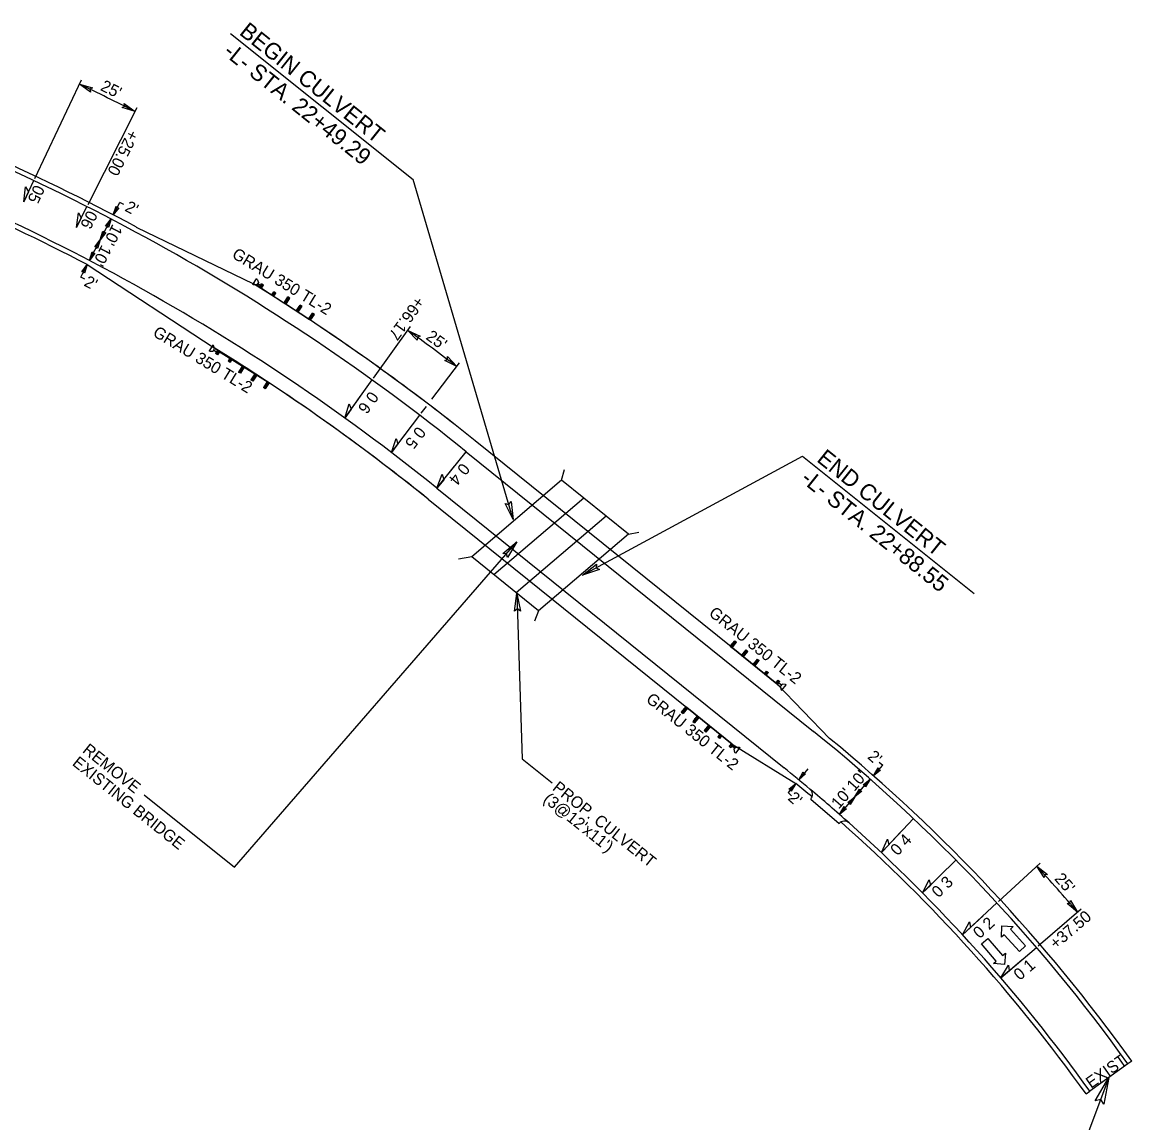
# Model space of a CAD drawing. Extents: x 1734344 to 1735097, y 915059 to 915850.
# Drawn here: x 1734622.6 to 1735096.6, y 915380.2 to 915850.3 of the extents above; entities that cross this region are included whole.
import ezdxf

# ---------------------------------------------------------------- set-up
doc = ezdxf.new("R2010")
doc.units = 0
for name, color, linetype in [('Prop Dimension Text', 7, 'Continuous'), ('Prop DSN Text', 7, 'Continuous'), ('Prop EOT', 7, 'Continuous'), ('Prop Guardrail', 7, 'Continuous'), ('Prop Guardrail Anchor Unit CELL', 7, 'Continuous'), ('Prop Lane Arrow CELL', 7, 'Continuous'), ('Prop Lane Lines', 7, 'Continuous'), ('Prop Paved Shoulder', 7, 'Continuous'), ('Prop Roadway Bridge', 7, 'Continuous'), ('Prop Roadway Culvert', 7, 'Continuous'), ('Prop Superelevation  Arrow CELL', 7, 'Continuous'), ('Prop Superelevation Label', 7, 'Continuous')]:
    doc.layers.add(name, color=color, linetype=linetype)

msp = doc.modelspace()

# ---------------------------------------------------------------- linework, layer by layer
at = {"layer": 'Prop Dimension Text'}
for p, q in [((1734628.03, 915783.6), (1734647.92, 915825.64)), ((1734650.75, 915772.47), (1734671.78, 915813.95)), ((1734661.54, 915768.03), (1734664.32, 915773.35)), ((1734666.09, 915772.42), (1734664.32, 915773.35)), ((1734655.98, 915757.4), (1734660.61, 915766.26)), ((1734651.35, 915748.54), (1734655.98, 915757.4)), ((1734647.64, 915741.45), (1734650.42, 915746.76)), ((1734649.41, 915740.52), (1734647.64, 915741.45)), ((1734772.69, 915698.31), (1734788.52, 915720.31)), ((1734797.66, 915689.34), (1734809.45, 915704.82)), ((1734793.03, 915683.26), (1734795.3, 915686.24)), ((1734958.13, 915531.38), (1734954.31, 915526.75)), ((1734986.19, 915528.48), (1734990.16, 915532.98)), ((1734988.65, 915534.31), (1734990.16, 915532.98)), ((1734953.04, 915525.2), (1734949.78, 915521.26)), ((1734978.26, 915519.47), (1734984.87, 915526.98)), ((1734949.78, 915521.26), (1734951.26, 915519.95)), ((1734971.65, 915511.97), (1734978.26, 915519.47)), ((1735039.68, 915474.79), (1735057.45, 915491.15)), ((1735056.55, 915455.82), (1735074.88, 915471.56))]:
    msp.add_line(p, q, dxfattribs=at)
for centre, radius, start, end in [((1734232.02, 914946.54), 970.51, 63.11588, 64.68134), ((1734232.02, 914946.54), 951.11, 52.71059, 54.27605), ((1734505.77, 914982.84), 748.16, 40.65421, 42.65756)]:
    msp.add_arc(centre, radius, start, end, dxfattribs=at)
at = {"layer": 'Prop DSN Text'}
for p, q in [((1734711.64, 915845.44), (1734789.56, 915783.08)), ((1734832.37, 915637.89), (1734789.56, 915783.08)), ((1734861.88, 915614.11), (1734955.89, 915664.98)), ((1734955.89, 915664.98), (1735029.28, 915606.25)), ((1734713.31, 915489.41), (1734833.87, 915628.32)), ((1734833.97, 915606.36), (1734836.16, 915535.68)), ((1734836.16, 915535.68), (1734848.98, 915525.41)), ((1734674.76, 915520.27), (1734713.31, 915489.41)), ((1735086.81, 915399.52), (1734968.27, 915084.45))]:
    msp.add_line(p, q, dxfattribs=at)
for points in [[(1734651.79, 915820.49), (1734647.06, 915823.83), (1734652.64, 915822.3), (1734651.58, 915821.69)], [(1734666.24, 915815.64), (1734670.87, 915812.17), (1734665.33, 915813.85), (1734666.41, 915814.43)], [(1734663.89, 915771.09), (1734661.54, 915768.03), (1734662.71, 915771.71), (1734663.09, 915770.99)], [(1734658.26, 915763.2), (1734660.61, 915766.26), (1734659.44, 915762.58), (1734659.07, 915763.3)], [(1734653.63, 915754.34), (1734655.98, 915757.4), (1734654.81, 915753.72), (1734654.44, 915754.44)], [(1734658.33, 915760.46), (1734655.98, 915757.4), (1734657.15, 915761.08), (1734657.53, 915760.35)], [(1734653.7, 915751.6), (1734651.35, 915748.54), (1734652.52, 915752.21), (1734652.89, 915751.49)], [(1734648.07, 915743.7), (1734650.42, 915746.76), (1734649.25, 915743.09), (1734648.88, 915743.81)], [(1734791.4, 915714.55), (1734787.35, 915718.69), (1734792.57, 915716.17), (1734791.41, 915715.77)], [(1734804.31, 915707.48), (1734808.24, 915703.23), (1734803.1, 915705.89), (1734804.26, 915706.26)], [(1734831.5, 915645.56), (1734832.37, 915637.89), (1734828.94, 915644.8), (1734830.48, 915644.28)], [(1734827.88, 915623.45), (1734833.87, 915628.32), (1734829.89, 915621.71), (1734829.5, 915623.28)], [(1734869.2, 915616.55), (1734861.88, 915614.11), (1734867.93, 915618.9), (1734867.75, 915617.28)], [(1734832.87, 915598.72), (1734833.97, 915606.36), (1734835.54, 915598.8), (1734834.18, 915599.7)], [(1734957.24, 915529.26), (1734954.31, 915526.75), (1734956.21, 915530.1), (1734956.43, 915529.32)], [(1734989.2, 915530.89), (1734986.19, 915528.48), (1734988.2, 915531.77), (1734988.39, 915530.98)], [(1734950.1, 915522.7), (1734953.04, 915525.2), (1734951.13, 915521.85), (1734950.92, 915522.63)], [(1734981.86, 915524.57), (1734984.87, 915526.98), (1734982.86, 915523.68), (1734982.66, 915524.48)], [(1734981.27, 915521.89), (1734978.26, 915519.47), (1734980.27, 915522.77), (1734980.46, 915521.98)], [(1734975.25, 915517.06), (1734978.26, 915519.47), (1734976.25, 915516.18), (1734976.06, 915516.97)], [(1734974.67, 915514.38), (1734971.65, 915511.97), (1734973.66, 915515.26), (1734973.86, 915514.47)], [(1735059.11, 915484.93), (1735055.98, 915489.8), (1735060.58, 915486.28), (1735059.37, 915486.12)], [(1735070.41, 915475.23), (1735073.36, 915470.25), (1735068.89, 915473.93), (1735070.1, 915474.05)], [(1735080.91, 915389.55), (1735086.81, 915399.52), (1735084.66, 915388.14), (1735083.28, 915390.16)]]:
    msp.add_lwpolyline(points, close=True, dxfattribs=at)
at = {"layer": 'Prop EOT'}
for p, q in [((1734812.32, 915666.88), (1734960.6, 915547.42)), ((1734799.77, 915651.3), (1734948.05, 915531.85)), ((1734959.45, 915518.49), (1734971.54, 915508.01)), ((1735094.93, 915405.35), (1735078.68, 915393.69))]:
    msp.add_line(p, q, dxfattribs=at)
for centre, radius, start, end in [((1734232.02, 914946.54), 925, 51.14521, 70.94317), ((1734232.02, 914946.54), 905, 51.14521, 70.94317), ((1734505.77, 914982.84), 725, 35.64584, 51.14521), ((1734505.77, 914982.84), 705, 49.98158, 51.14521), ((1734957.18, 915520.46), 3, 319.0837, 49.9816), ((1734973.81, 915506.05), 3, 48.1859, 139.0837), ((1734505.77, 914982.84), 705, 35.64584, 48.18591)]:
    msp.add_arc(centre, radius, start, end, dxfattribs=at)
at = {"layer": 'Prop Guardrail'}
for p, q in [((1734925.43, 915583.46), (1734816.08, 915671.55)), ((1734796.01, 915646.63), (1734906.46, 915557.65))]:
    msp.add_line(p, q, dxfattribs=at)
for radius in [931.01, 899]:
    msp.add_arc((1734232.02, 914946.54), radius, 51.14521, 56.54095, dxfattribs=at)
at = {"layer": 'Prop Guardrail Anchor Unit CELL'}
for p, q in [((1734721.12, 915738.26), (1734722.75, 915740.71)), ((1734723.01, 915740.54), (1734722.75, 915740.71)), ((1734723.51, 915739.18), (1734722.84, 915738.16)), ((1734723.01, 915740.54), (1734723.51, 915739.18)), ((1734723.23, 915738.76), (1734724.46, 915737.95)), ((1734724.06, 915737.34), (1734724.89, 915738.6)), ((1734725.73, 915738.05), (1734724.89, 915738.6)), ((1734724.89, 915736.78), (1734724.89, 915738.6)), ((1734721.38, 915738.09), (1734721.12, 915738.26)), ((1734722.84, 915738.16), (1734721.38, 915738.09)), ((1734724.06, 915737.34), (1734722.84, 915738.16)), ((1734725.73, 915738.05), (1734724.06, 915737.34)), ((1734724.89, 915736.78), (1734724.06, 915737.34)), ((1734724.47, 915737.06), (1734745.32, 915723.27)), ((1734724.89, 915736.78), (1734725.73, 915738.05)), ((1734729.27, 915733.89), (1734730.11, 915735.15)), ((1734730.94, 915734.6), (1734729.27, 915733.89)), ((1734730.1, 915733.34), (1734729.27, 915733.89)), ((1734730.1, 915733.34), (1734730.11, 915735.15)), ((1734730.1, 915733.34), (1734730.94, 915734.6)), ((1734730.94, 915734.6), (1734730.11, 915735.15)), ((1734734.48, 915730.44), (1734736.16, 915732.97)), ((1734736.15, 915731.15), (1734734.48, 915730.44)), ((1734735.32, 915729.89), (1734734.48, 915730.44)), ((1734735.32, 915729.89), (1734736.99, 915732.42)), ((1734735.32, 915731.71), (1734736.99, 915732.42)), ((1734736.15, 915731.15), (1734735.32, 915731.71)), ((1734735.32, 915729.89), (1734735.32, 915731.71)), ((1734736.16, 915732.97), (1734736.15, 915731.15)), ((1734736.99, 915732.42), (1734736.16, 915732.97)), ((1734739.69, 915726.99), (1734741.37, 915729.52)), ((1734740.53, 915726.44), (1734742.2, 915728.97)), ((1734740.53, 915728.26), (1734742.2, 915728.97)), ((1734742.2, 915728.97), (1734741.37, 915729.52)), ((1734741.37, 915729.52), (1734741.37, 915727.71)), ((1734741.37, 915727.71), (1734739.69, 915726.99)), ((1734740.53, 915726.44), (1734739.69, 915726.99)), ((1734741.37, 915727.71), (1734740.53, 915728.26)), ((1734740.53, 915726.44), (1734740.53, 915728.26)), ((1734744.91, 915723.54), (1734746.58, 915726.08)), ((1734746.58, 915724.26), (1734744.91, 915723.54)), ((1734745.74, 915722.99), (1734747.42, 915725.52)), ((1734745.74, 915724.81), (1734747.42, 915725.52)), ((1734746.58, 915724.26), (1734745.74, 915724.81)), ((1734745.74, 915722.99), (1734745.74, 915724.81)), ((1734747.42, 915725.52), (1734746.58, 915726.08)), ((1734746.58, 915726.08), (1734746.58, 915724.26)), ((1734745.74, 915722.99), (1734744.91, 915723.54)), ((1734704.02, 915712.41), (1734702.46, 915709.92)), ((1734702.72, 915709.75), (1734702.46, 915709.92)), ((1734702.72, 915709.75), (1734704.17, 915709.85)), ((1734704.28, 915712.24), (1734704.02, 915712.41)), ((1734704.17, 915709.85), (1734704.83, 915710.89)), ((1734704.82, 915710.89), (1734704.28, 915712.24)), ((1734704.44, 915710.28), (1734705.69, 915709.5)), ((1734706.07, 915710.11), (1734704.82, 915710.89)), ((1734706.08, 915710.12), (1734705.27, 915708.83)), ((1734706.92, 915709.59), (1734706.08, 915710.12)), ((1734706.12, 915708.3), (1734706.08, 915710.12)), ((1734706.5, 915709.85), (1734727.67, 915696.56)), ((1734706.92, 915709.59), (1734705.27, 915708.83)), ((1734706.12, 915708.3), (1734705.27, 915708.83)), ((1734706.92, 915709.59), (1734706.12, 915708.3)), ((1734711.37, 915706.8), (1734710.56, 915705.51)), ((1734712.22, 915706.27), (1734710.56, 915705.51)), ((1734711.41, 915704.98), (1734710.56, 915705.51)), ((1734712.22, 915706.27), (1734711.37, 915706.8)), ((1734711.41, 915704.98), (1734711.37, 915706.8)), ((1734712.22, 915706.27), (1734711.41, 915704.98)), ((1734716.66, 915703.47), (1734715.05, 915700.9)), ((1734715.05, 915700.9), (1734716.7, 915701.66)), ((1734715.9, 915700.37), (1734715.05, 915700.9)), ((1734717.51, 915702.94), (1734715.86, 915702.19)), ((1734716.7, 915701.66), (1734715.86, 915702.19)), ((1734715.86, 915702.19), (1734715.9, 915700.37)), ((1734717.51, 915702.94), (1734715.9, 915700.37)), ((1734717.51, 915702.94), (1734716.66, 915703.47)), ((1734716.7, 915701.66), (1734716.66, 915703.47)), ((1734721.96, 915700.15), (1734720.34, 915697.58)), ((1734720.34, 915697.58), (1734722, 915698.33)), ((1734721.19, 915697.05), (1734720.34, 915697.58)), ((1734722.81, 915699.62), (1734721.15, 915698.87)), ((1734722, 915698.33), (1734721.15, 915698.87)), ((1734721.15, 915698.87), (1734721.19, 915697.05)), ((1734722.81, 915699.62), (1734721.19, 915697.05)), ((1734722.81, 915699.62), (1734721.96, 915700.15)), ((1734722, 915698.33), (1734721.96, 915700.15)), ((1734727.25, 915696.83), (1734725.64, 915694.26)), ((1734728.1, 915696.3), (1734726.44, 915695.54)), ((1734728.1, 915696.3), (1734726.48, 915693.73)), ((1734728.1, 915696.3), (1734727.25, 915696.83)), ((1734727.29, 915695.01), (1734727.25, 915696.83)), ((1734725.64, 915694.26), (1734727.29, 915695.01)), ((1734726.48, 915693.73), (1734725.64, 915694.26)), ((1734727.29, 915695.01), (1734726.44, 915695.54)), ((1734726.44, 915695.54), (1734726.48, 915693.73)), ((1734925.04, 915583.78), (1734926.94, 915586.14)), ((1734925.04, 915583.78), (1734926.77, 915584.33)), ((1734925.04, 915583.78), (1734925.82, 915583.15)), ((1734944.89, 915567.78), (1734925.43, 915583.46)), ((1734925.82, 915583.15), (1734927.72, 915585.51)), ((1734925.99, 915584.96), (1734925.82, 915583.15)), ((1734927.72, 915585.51), (1734925.99, 915584.96)), ((1734925.99, 915584.96), (1734926.77, 915584.33)), ((1734926.77, 915584.33), (1734926.94, 915586.14)), ((1734926.94, 915586.14), (1734927.72, 915585.51)), ((1734929.9, 915579.86), (1734931.81, 915582.22)), ((1734931.64, 915580.41), (1734931.81, 915582.22)), ((1734931.81, 915582.22), (1734932.59, 915581.59)), ((1734929.9, 915579.86), (1734931.64, 915580.41)), ((1734929.9, 915579.86), (1734930.68, 915579.23)), ((1734930.68, 915579.23), (1734932.59, 915581.59)), ((1734930.86, 915581.04), (1734930.68, 915579.23)), ((1734932.59, 915581.59), (1734930.86, 915581.04)), ((1734930.86, 915581.04), (1734931.64, 915580.41)), ((1734934.77, 915575.93), (1734936.68, 915578.3)), ((1734935.55, 915575.31), (1734937.45, 915577.67)), ((1734937.45, 915577.67), (1734935.72, 915577.12)), ((1734936.5, 915576.49), (1734936.68, 915578.3)), ((1734936.68, 915578.3), (1734937.45, 915577.67)), ((1734934.77, 915575.93), (1734936.5, 915576.49)), ((1734934.77, 915575.93), (1734935.55, 915575.31)), ((1734935.72, 915577.12), (1734935.55, 915575.31)), ((1734935.72, 915577.12), (1734936.5, 915576.49)), ((1734939.64, 915572.01), (1734940.59, 915573.2)), ((1734939.64, 915572.01), (1734941.37, 915572.57)), ((1734940.59, 915573.2), (1734940.42, 915571.39)), ((1734940.42, 915571.39), (1734941.37, 915572.57)), ((1734940.59, 915573.2), (1734941.37, 915572.57)), ((1734939.64, 915572.01), (1734940.42, 915571.39)), ((1734944.51, 915568.09), (1734945.46, 915569.27)), ((1734944.51, 915568.09), (1734946.24, 915568.65)), ((1734944.51, 915568.09), (1734945.28, 915567.46)), ((1734945.46, 915569.27), (1734945.28, 915567.46)), ((1734945.28, 915567.46), (1734946.24, 915568.65)), ((1734945.46, 915569.27), (1734946.24, 915568.65)), ((1734946.89, 915567.11), (1734945.74, 915568.03)), ((1734945.29, 915567.47), (1734946.44, 915566.55)), ((1734947.2, 915567.51), (1734946.44, 915566.55)), ((1734946.44, 915566.55), (1734946.82, 915565.14)), ((1734946.82, 915565.14), (1734947.06, 915564.95)), ((1734947.06, 915564.95), (1734948.9, 915567.24)), ((1734948.66, 915567.44), (1734947.2, 915567.51)), ((1734948.66, 915567.44), (1734948.9, 915567.24)), ((1734906.07, 915557.97), (1734904.16, 915555.6)), ((1734905.89, 915556.16), (1734904.16, 915555.6)), ((1734904.16, 915555.6), (1734904.94, 915554.98)), ((1734906.85, 915557.34), (1734904.94, 915554.98)), ((1734904.94, 915554.98), (1734905.11, 915556.78)), ((1734905.11, 915556.78), (1734906.85, 915557.34)), ((1734905.11, 915556.78), (1734905.89, 915556.16)), ((1734906.07, 915557.97), (1734905.89, 915556.16)), ((1734906.07, 915557.97), (1734906.85, 915557.34)), ((1734925.92, 915541.97), (1734906.46, 915557.65)), ((1734910.93, 915554.05), (1734909.03, 915551.68)), ((1734910.93, 915554.05), (1734910.76, 915552.24)), ((1734910.93, 915554.05), (1734911.71, 915553.42)), ((1734910.76, 915552.24), (1734909.03, 915551.68)), ((1734909.03, 915551.68), (1734909.81, 915551.05)), ((1734911.71, 915553.42), (1734909.81, 915551.05)), ((1734909.81, 915551.05), (1734909.98, 915552.86)), ((1734909.98, 915552.86), (1734911.71, 915553.42)), ((1734909.98, 915552.86), (1734910.76, 915552.24)), ((1734915.8, 915550.12), (1734913.9, 915547.76)), ((1734916.58, 915549.5), (1734914.67, 915547.13)), ((1734914.67, 915547.13), (1734914.85, 915548.94)), ((1734914.85, 915548.94), (1734916.58, 915549.5)), ((1734914.85, 915548.94), (1734915.63, 915548.31)), ((1734915.8, 915550.12), (1734915.63, 915548.31)), ((1734915.8, 915550.12), (1734916.58, 915549.5)), ((1734915.63, 915548.31), (1734913.9, 915547.76)), ((1734913.9, 915547.76), (1734914.67, 915547.13)), ((1734920.67, 915546.2), (1734919.71, 915545.02)), ((1734919.71, 915545.02), (1734920.49, 915544.39)), ((1734919.72, 915545.02), (1734921.45, 915545.58)), ((1734920.67, 915546.2), (1734920.49, 915544.39)), ((1734921.45, 915545.58), (1734920.49, 915544.39)), ((1734920.67, 915546.2), (1734921.45, 915545.58)), ((1734925.53, 915542.28), (1734924.58, 915541.1)), ((1734924.58, 915541.1), (1734926.31, 915541.66)), ((1734924.58, 915541.1), (1734925.36, 915540.47)), ((1734925.53, 915542.28), (1734925.36, 915540.47)), ((1734926.31, 915541.66), (1734925.36, 915540.47)), ((1734925.53, 915542.28), (1734926.31, 915541.66)), ((1734927, 915540.16), (1734925.86, 915541.09)), ((1734926.31, 915541.65), (1734927.45, 915540.72)), ((1734926.68, 915539.77), (1734927.45, 915540.72)), ((1734927.06, 915538.37), (1734926.68, 915539.77)), ((1734929.15, 915540.46), (1734927.3, 915538.17)), ((1734927.45, 915540.72), (1734928.91, 915540.65)), ((1734928.91, 915540.65), (1734929.15, 915540.46)), ((1734927.06, 915538.37), (1734927.3, 915538.17))]:
    msp.add_line(p, q, dxfattribs=at)
at = {"layer": 'Prop Lane Arrow CELL'}
for points in [[(1735048.53, 915453.35), (1735042.05, 915460.55), (1735040.85, 915459.47), (1735041.11, 915464.31), (1735045.94, 915464.05), (1735044.74, 915462.97), (1735051.22, 915455.77)], [(1735035.03, 915459), (1735041.38, 915451.68), (1735042.6, 915452.74), (1735042.25, 915447.91), (1735037.42, 915448.25), (1735038.64, 915449.31), (1735032.29, 915456.63)]]:
    msp.add_lwpolyline(points, close=True, dxfattribs=at)
at = {"layer": 'Prop Lane Lines'}
msp.add_arc((1734505.77, 914982.84), 705, 48.18591, 49.98158, dxfattribs=at)
at = {"layer": 'Prop Paved Shoulder'}
for p, q in [((1734671.39, 915762.8), (1734721.46, 915738.51)), ((1734650.42, 915746.76), (1734704.64, 915711.29)), ((1734925.43, 915583.46), (1734816.08, 915671.55)), ((1734796.01, 915646.63), (1734906.46, 915557.65)), ((1734925.43, 915583.46), (1734944.89, 915567.78)), ((1734944.89, 915567.78), (1734967.51, 915544.38)), ((1734906.46, 915557.65), (1734925.92, 915541.97)), ((1734925.92, 915541.97), (1734953.04, 915525.2)), ((1735096.56, 915406.51), (1735094.93, 915405.35)), ((1735077.05, 915392.53), (1735078.68, 915393.69))]:
    msp.add_line(p, q, dxfattribs=at)
for centre, radius, start, end in [((1734232.02, 914946.54), 927, 61.70734, 70.94317), ((1734232.02, 914946.54), 903, 62.39682, 70.94317), ((1734232.02, 914946.54), 931, 51.14521, 58.2837), ((1734232.02, 914946.54), 899, 51.14521, 58.2837), ((1734505.77, 914982.84), 727, 35.64584, 50.57045), ((1734505.77, 914982.84), 703, 49.7509, 50.48914), ((1734505.77, 914982.84), 703, 35.64584, 48.4166)]:
    msp.add_arc(centre, radius, start, end, dxfattribs=at)
at = {"layer": 'Prop Roadway Bridge'}
for p, q in [((1734853.04, 915654.7), (1734854.21, 915659.31)), ((1734853.04, 915654.69), (1734814.63, 915621.95)), ((1734862.55, 915647.03), (1734824.14, 915614.29)), ((1734872.06, 915639.37), (1734833.65, 915606.62)), ((1734881.57, 915631.71), (1734843.16, 915598.96)), ((1734881.57, 915631.71), (1734886, 915632.47)), ((1734814.63, 915621.95), (1734809.01, 915620.95)), ((1734843.16, 915598.96), (1734841.46, 915594.48))]:
    msp.add_line(p, q, dxfattribs=at)
at = {"layer": 'Prop Roadway Culvert'}
for p, q in [((1734881.57, 915631.71), (1734853.04, 915654.7)), ((1734843.16, 915598.96), (1734814.63, 915621.95))]:
    msp.add_line(p, q, dxfattribs=at)
at = {"layer": 'Prop Superelevation  Arrow CELL'}
for p, q in [((1734623.32, 915773.65), (1734627.6, 915782.69)), ((1734645.77, 915762.65), (1734650.29, 915771.57)), ((1734760.43, 915681.26), (1734767.44, 915691)), ((1734780.31, 915666.55), (1734787.58, 915676.1)), ((1734799.77, 915651.3), (1734807.3, 915660.65)), ((1734989.59, 915495.62), (1734997.83, 915504.34)), ((1735007.22, 915478.39), (1735015.76, 915486.82)), ((1735024.24, 915460.56), (1735033.07, 915468.69)), ((1735040.62, 915442.14), (1735049.73, 915449.96))]:
    msp.add_line(p, q, dxfattribs=at)
for points in [[(1734623.32, 915773.65), (1734624.08, 915779.93), (1734625.3, 915777.83)], [(1734645.77, 915762.65), (1734646.7, 915768.91), (1734647.86, 915766.78)], [(1734760.43, 915681.26), (1734762.31, 915687.3), (1734763.13, 915685.01)], [(1734780.31, 915666.55), (1734782.35, 915672.53), (1734783.11, 915670.23)], [(1734799.77, 915651.3), (1734801.98, 915657.23), (1734802.67, 915654.9)], [(1734989.59, 915495.62), (1734992.26, 915501.35), (1734992.77, 915498.98)], [(1735007.22, 915478.39), (1735010.08, 915484.03), (1735010.51, 915481.64)], [(1735024.24, 915460.56), (1735027.3, 915466.09), (1735027.64, 915463.69)], [(1735040.62, 915442.14), (1735043.87, 915447.57), (1735044.13, 915445.15)]]:
    msp.add_lwpolyline(points, close=True, dxfattribs=at)
at = {"layer": 'Prop Superelevation Label'}
for p, q in [((1734623.32, 915773.65), (1734627.6, 915782.69)), ((1734645.77, 915762.65), (1734650.29, 915771.57)), ((1734760.43, 915681.26), (1734772.11, 915697.5)), ((1734780.31, 915666.55), (1734792.42, 915682.46)), ((1734799.77, 915651.3), (1734812.32, 915666.88)), ((1734989.59, 915495.62), (1735003.32, 915510.16)), ((1735021.45, 915492.45), (1735007.22, 915478.39)), ((1735024.24, 915460.56), (1735038.95, 915474.11)), ((1735040.62, 915442.14), (1735055.8, 915455.17))]:
    msp.add_line(p, q, dxfattribs=at)

# ---------------------------------------------------------------- texts
at = {"layer": 'Prop Dimension Text'}
for s, rotation, p in [("25'", 333.8986, (1734655.69, 915821.42)), ('+25.00', 243.1159, (1734668.2, 915804.81)), ("2'", 332.3968, (1734666.14, 915769.9)), ("10'", 242.3968, (1734661.33, 915764.4)), ("10'", 242.3968, (1734656.7, 915755.53)), ("2'", 332.3968, (1734648.67, 915737.93)), ('+66.17', 234.276, (1734790.87, 915733.61)), ("25'", 323.4933, (1734794.71, 915715.22)), ("2'", 318.6373, (1734983.36, 915536.13)), ("10'", 48.6373, (1734978.01, 915521.46)), ("2'", 318.6373, (1734949.32, 915518.44)), ("10'", 48.6373, (1734971.4, 915513.95)), ("25'", 311.6559, (1735063.22, 915484.3)), ('+37.50', 40.6542, (1735064.12, 915454.1))]:
    msp.add_text(s, height=5, rotation=rotation, dxfattribs=at).set_placement(p)
at = {"layer": 'Prop DSN Text'}
for s, height, p in [('BEGIN CULVERT', 7, (1734714.97, 915845.34)), ('-L- STA. 22+49.29', 7, (1734708.1, 915836.75)), ('END CULVERT', 7, (1734961.59, 915662.99)), ('-L- STA. 22+88.55', 7, (1734954.72, 915654.4)), ('REMOVE', 5, (1734648.06, 915538.74)), ('EXISTING BRIDGE', 5, (1734643.69, 915533.27)), ('PROP. CULVERT', 5, (1734848.76, 915522.66)), ("(3@12'x11')", 5, (1734844.8, 915517.71))]:
    msp.add_text(s, height=height, rotation=321.3297, dxfattribs=at).set_placement(p)
at = {"layer": 'Prop Guardrail Anchor Unit CELL'}
for rotation, p in [(328.5992, (1734711.86, 915749.99)), (328.5992, (1734678.05, 915716.58)), (321.3297, (1734915.54, 915597.22)), (321.3297, (1734888.7, 915560.43))]:
    msp.add_text('GRAU 350 TL-2', height=5, rotation=rotation, dxfattribs=at).set_placement(p)
at = {"layer": 'Prop Superelevation Label'}
for s, rotation, p in [('05', 244.6813, (1734627.97, 915781.25)), ('06', 243.1159, (1734650.66, 915770.32)), ('0 6', 234.276, (1734771.19, 915693.05)), ('0 5', 232.7106, (1734791.46, 915678.01)), ('0 4', 231.1452, (1734810.38, 915662.41)), ('0 4', 46.6643, (1734996.54, 915493.98)), ('0 3', 44.6609, (1735014.03, 915476.04)), ('0 2', 42.6576, (1735031.56, 915458.62)), ('0 1', 40.6542, (1735048.72, 915440.78)), ('EXIST', 35.1459, (1735079.15, 915394.68))]:
    msp.add_text(s, height=5, rotation=rotation, dxfattribs=at).set_placement(p)

doc.saveas('drawing.dxf')
